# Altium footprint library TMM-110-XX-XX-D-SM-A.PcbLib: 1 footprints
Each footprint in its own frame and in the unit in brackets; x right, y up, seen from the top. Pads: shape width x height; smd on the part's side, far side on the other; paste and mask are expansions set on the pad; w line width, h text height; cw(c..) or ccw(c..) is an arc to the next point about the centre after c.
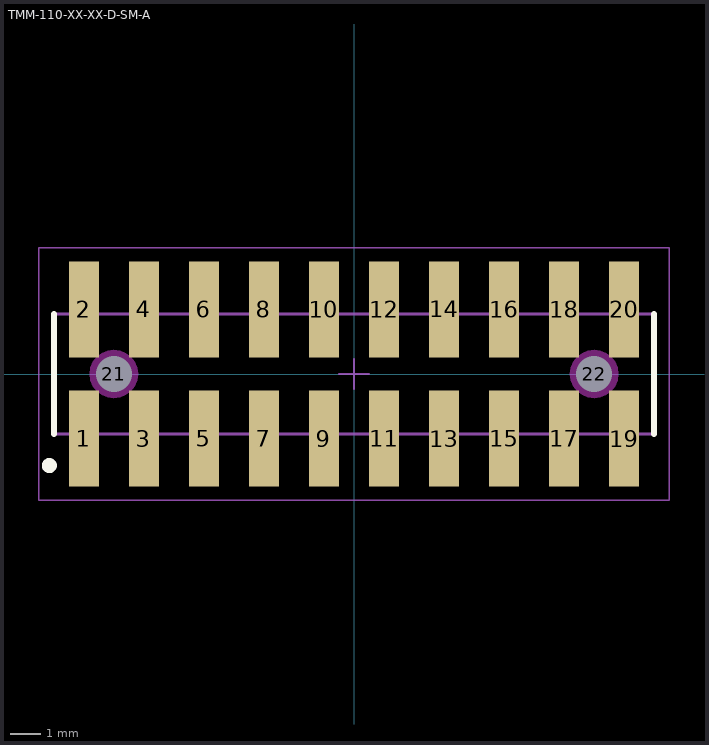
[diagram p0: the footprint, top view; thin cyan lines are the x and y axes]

## TMM-110-XX-XX-D-SM-A [mm] "2.00mm pitch, 20 pin, terminal strip; double row, w/alignment pins, SMT"
height 2.77
pads (22):
  rect 1x3.2 smd mask+0: 1(-9,-2.15) 2(-9,2.15) 3(-7,-2.15) 4(-7,2.15) 5(-5,-2.15) 6(-5,2.15) 7(-3,-2.15) 8(-3,2.15) 9(-1,-2.15) 10(-1,2.15) 11(1,-2.15) 12(1,2.15) 13(3,-2.15) 14(3,2.15) 15(5,-2.15) 16(5,2.15) 17(7,-2.15) 18(7,2.15) 19(9,-2.15) 20(9,2.15)
  round 1 hole 1.2 unplated mask+0: 21(-8,0) 22(8,0)
Top Overlay:
  circle w0.25: c-10.15,-3.05 r0.125
  lines w0.2: -10,-2 -10,2 ; 10,-2 10,2
Keep-Out Layer:
  pour cut-out: -7.193,0 -7.221,0.209 -7.301,0.403 -7.429,0.571 -7.597,0.699 -7.791,0.779 -8,0.807 -8.209,0.779 -8.403,0.699 -8.571,0.571 -8.699,0.403 -8.779,0.209 -8.807,0 -8.779,-0.209 -8.699,-0.403 -8.571,-0.571 -8.403,-0.699 -8.209,-0.779 -8,-0.807 -7.791,-0.779 -7.597,-0.699 -7.429,-0.571 -7.301,-0.403 -7.221,-0.209
  pour cut-out: 8.807,0 8.779,0.209 8.699,0.403 8.571,0.571 8.403,0.699 8.209,0.779 8,0.807 7.791,0.779 7.597,0.699 7.429,0.571 7.301,0.403 7.221,0.209 7.193,0 7.221,-0.209 7.301,-0.403 7.429,-0.571 7.597,-0.699 7.791,-0.779 8,-0.807 8.209,-0.779 8.403,-0.699 8.571,-0.571 8.699,-0.403 8.779,-0.209
Mechanical 12:
  lines w0.001: -10,-2 10,-2 10,2 -10,2 -10,-2
Mechanical 13:
  lines w0.1: -10,-2 10,-2 10,2 -10,2 -10,-2
  text ".Designator" at 0,-0.127 h1.52
Mechanical 15:
  lines w0.05: -0.5,0 0.5,0 ; 0,-0.5 0,0.5 ; -10.5,-4.2 10.5,-4.2 10.5,4.2 -10.5,4.2 -10.5,-4.2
